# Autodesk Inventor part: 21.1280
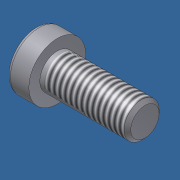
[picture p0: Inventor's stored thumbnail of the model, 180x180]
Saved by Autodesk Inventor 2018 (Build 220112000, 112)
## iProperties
Created: 2006-02
Part Number: 21.1280
Material: Steel, Mild
Description: M8X22 SHCS
Document SubType Name: Modeling
Standard: DIN 7984
Designer: Andy Moles
Standards Organization: DIN
Language: en-US
Size Designation: M8 x 20
Categories: <MemberInstance><Categories><Category DisplayName="Fasteners" InternalName="e4da775c-781d-43d5-af7c-5136215cf5a6" Mnemonic="FSTN"><Category DisplayName="Bolts"
Density: 7.85 g/cm^3
Mass: 13.0366 g
Surface Area: 10.6794 cm^2
Volume: 1.66071 cm^3
Vendor: S
Appearance: Zinc
Author: Andy Moles
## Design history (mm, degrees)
sketch "Sketch1"
  geometry: L1 (0.467, 0)-(22, 0); L2 (22, 0)-(22, 4); L3 (22, 4)-(1, 4); L4 (1, 4)-(0.233, 4); L5 (0.233, 4)-(0, 4); L6 (0, 4)-(0, 6.5); L7 (0, 6.5)-(-5, 6.5); L8 (-5, 6.5)-(-5, 2.887); L9 (-5, 2.887)-(-1.2, 2.887); L10 (-1.2, 2.887)-(0.467, 0); L11 (-7.5, 0)-(27.5, 0) reference; L12 (0, -0.65)-(0, 8.45) reference; L13 (1, 4)-(0, 4)
  constraints: 22 end point, 6 parallel, 2 collinear, 2 perpendicular, 1 horizontal, 1 point on line
  dimensions: "d1" = 21 distance from line of L3.end L2 (= GEL); "d2" = 0.76691 distance of L4.end L3.end (computed from GAL); "d3" = 5 distance between parallel lines of L8 L6 (= KOH); "d4" = 3.8 distance of L8.end L9.end (= INTI); "d5" = 60 deg angle of L10 L1; "d6" = 8 diameter of L3 L1 (= GD); "d7" = 8 diameter of L5 L1 (= BDM); "d8" = 5.7735 diameter of L9 L1 (= 1.1547 x SW); "d9" = 13 diameter of L7 L1 (= KOD); "d26" = 22 distance between parallel lines of L12 L2 (= NLG)
revolve "Body" sketch "Sketch1" stored, may be unused: angle "d10" = 90 deg
sketch "Sketch2"
  geometry: L1 (0, -7.8)-(0, 10.4) reference; L2 (-7.8, 0)-(10.4, 0) reference; L3 (2.887, 0)-(1.443, -2.5); L4 (1.443, -2.5)-(-1.443, -2.5); L5 (-1.443, -2.5)-(-2.887, 0); L6 (-2.887, 0)-(-1.443, 2.5); L7 (-1.443, 2.5)-(1.443, 2.5); L8 (1.443, 2.5)-(2.887, 0); 2 further points
  constraints: 12 end point, 1 coincident, 1 horizontal alignment, 1 point on line, 12 other
extrude "Slot" join sketch "Sketch2" stored distance "d11" = 10; taper "d12" = 0 deg
workplane "Work Plane1"
body "Solid1"
fillet "Fillet1" dims "d17" = 0.8 (= RR)
feature "Thread" dims "d13" = 22, "d14" = 0
chamfer "Chamfer1" distance "d15" = 0.76681 (= -0.5 x SPD + 0.5 x GD); stored, may be unused: second distance "d16" = 0.76681 (= GUL), angle "d27" = 45 deg
other parameters: "GD" = 8 (= NND) [user parameter; used in 2 equation terms], "NLG" = 22 [user parameter; used in 1 equation term], "GEL" = 21 [user parameter; used in 1 equation term], "KOD" = 13 [user parameter; used in 1 equation term], "KOH" = 5 [user parameter; used in 1 equation term], "INTI" = 3.8 [user parameter; used in 1 equation term], "GAL" = 0.76681 (= 0.61345 x PTC) [user parameter; used in 1 equation term], "GUL" = 0.76681 (= 0.61345 x PTC) [user parameter; used in 1 equation term], "BDM" = 8 (= NND) [user parameter; used in 1 equation term], "SW" = 5 [user parameter; used in 2 equation terms], "RR" = 0.8 [user parameter; used in 1 equation term], "SPD" = 6.46637 (= NND - 1.2269 x PTC) [user parameter; used in 1 equation term], "d19" = 0, "d28" = 0, "d29" = 0, "TOA" = 30 deg [user parameter], "GD1" = 6.46637 (= THREADDIA - 1.2269 x PTC) [user parameter], "THREADDIA" = 8 [user parameter; used in 1 equation term], "FAWI" = 45 deg [user parameter], "ANG" = 120 deg [user parameter], "TPU" = 8 (computed from PTC) [user parameter], "PTC" = 1.25 [user parameter; used in 5 equation terms], "NND" = 8 [user parameter; used in 3 equation terms], "E0" = 5.775 (= 1.155 x SW) [user parameter]
